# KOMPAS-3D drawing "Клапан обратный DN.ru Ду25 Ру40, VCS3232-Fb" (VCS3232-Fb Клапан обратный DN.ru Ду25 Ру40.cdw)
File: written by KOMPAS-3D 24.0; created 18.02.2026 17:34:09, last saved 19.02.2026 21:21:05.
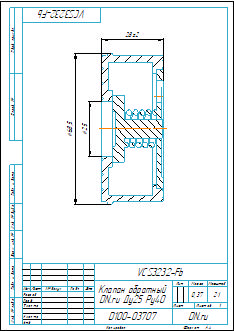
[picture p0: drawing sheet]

Document properties: v313: 1; D: 58; d: 20; a: 1; L: 28; Артикул: D100-03707; Автор: R2D2; Форматы листов документа: A4; Полное имя файла: VCS3232-Fb Клапан обратный DN.ru Ду25 Ру40.m3d; Масса: 0.37; Наименование: Клапан обратный DN.ru Ду25 Ру40; Количество листов документа: 1; Примечание: D100-03707

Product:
- Body: Тело 1  | qty 1
    Масса: 0.226516
- Body: Тело 2  | qty 1
    Масса: 0.075056
- Part/product: Клапан обратный DN.ru Ду25 Ру40  | designation VCS3232-Fb
    Масса: 0.37
    Примечание: D100-03707
    additional columns: 1; D100-03707

Views: Вид 1, Местный разрез 1, Справа
Referenced files in E:\Работа\Зайцев\VCS3232-Fb Клапан обратный DN.ru Ду15-100\DN25\: VCS3232-Fb Клапан обратный DN.ru Ду25 Ру40.m3d
Referenced files in E:\Работа\Зайцев\Для компаса\: чертеж DN.ru.cdt
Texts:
  VCS3232-Fb
  чертеж DN.ru.cdt
  Клапан обратный
  DN.ru Ду25 Ру40
  prop
  Клапан обратный DN.ru Ду25 Ру40
  VCS3232-Fb Клапан обратный DN.ru Ду25 Ру40
Dimensions and other numbers on the sheet: 0; 3; 2; 4; 28±2; 68,5; 25; 6; 2:1; 1; 0,37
